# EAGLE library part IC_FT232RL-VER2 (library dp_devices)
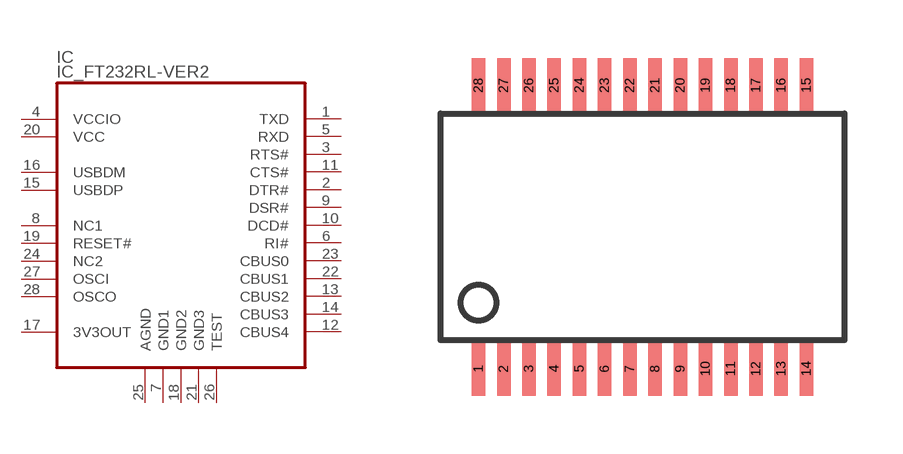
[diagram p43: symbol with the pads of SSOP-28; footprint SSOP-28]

Designator prefix IC

## IC_FT232RL-VER2  [SSOP-28]
1  TXD
2  DTR#
3  RTS#
4  VCCIO  pwr
5  RXD
6  RI#
7  GND1  pwr
8  NC1  nc
9  DSR#
10  DCD#
11  CTS#
12  CBUS4
13  CBUS2
14  CBUS3
15  USBDP
16  USBDM
17  3V3OUT  out
18  GND2  pwr
19  RESET#  in
20  VCC  pwr
21  GND3  pwr
22  CBUS1
23  CBUS0
24  NC2  nc
25  AGND  pwr
26  TEST  in
27  OSCI  in
28  OSCO  out

## Footprint SSOP-28 (pad centres in mm)
SSOP28
smd 0.348 x 1.397: 1 -4.225,-3.656; 2 -3.575,-3.656; 3 -2.925,-3.656; 4 -2.275,-3.656; 5 -1.625,-3.656; 6 -0.975,-3.656; 7 -0.325,-3.656; 8 0.325,-3.656; 9 0.975,-3.656; 10 1.625,-3.656; 11 2.275,-3.656; 12 2.925,-3.656; 13 3.575,-3.656; 14 4.225,-3.656; 15 4.225,3.656; 16 3.575,3.656; 17 2.925,3.656; 18 2.275,3.656; 19 1.625,3.656; 20 0.975,3.656; 21 0.325,3.656; 22 -0.325,3.656; 23 -0.975,3.656; 24 -1.625,3.656; 25 -2.275,3.656; 26 -2.925,3.656; 27 -3.575,3.656; 28 -4.225,3.656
